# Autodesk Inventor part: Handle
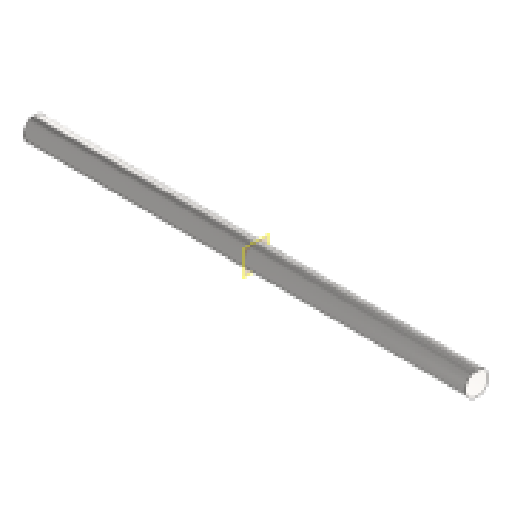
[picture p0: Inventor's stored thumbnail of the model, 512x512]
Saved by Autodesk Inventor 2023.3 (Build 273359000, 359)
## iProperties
Created: 2020-10
Part Number: Handle
Material: Steel, Mild
Document SubType Name: Modeling
Designer: User
Density: 7.85 g/cm^3
Appearance: Semi-Polished
Mass: 14.7969 g
Surface Area: 15.4723 cm^2
Volume: 1.88496 cm^3
Author: User
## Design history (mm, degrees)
sketch "Sketch1"
  geometry: L1 (0, 0)-(96, 0); L2 (96, 0)-(96, 2.5); L3 (96, 2.5)-(0, 2.5); L4 (0, 2.5)-(0, 0)
  constraints: 8 end point, 2 parallel, 1 horizontal, 1 perpendicular
  dimensions: "d0" = 96 distance of L3.end L2.end; "d1" = 2.5 distance of L2.end L1.end
revolve "Revolution1" sketch "Sketch1" stored, may be unused: angle "d2" = 90 deg
node "Piano di lavoro1"
body "Solid1"
